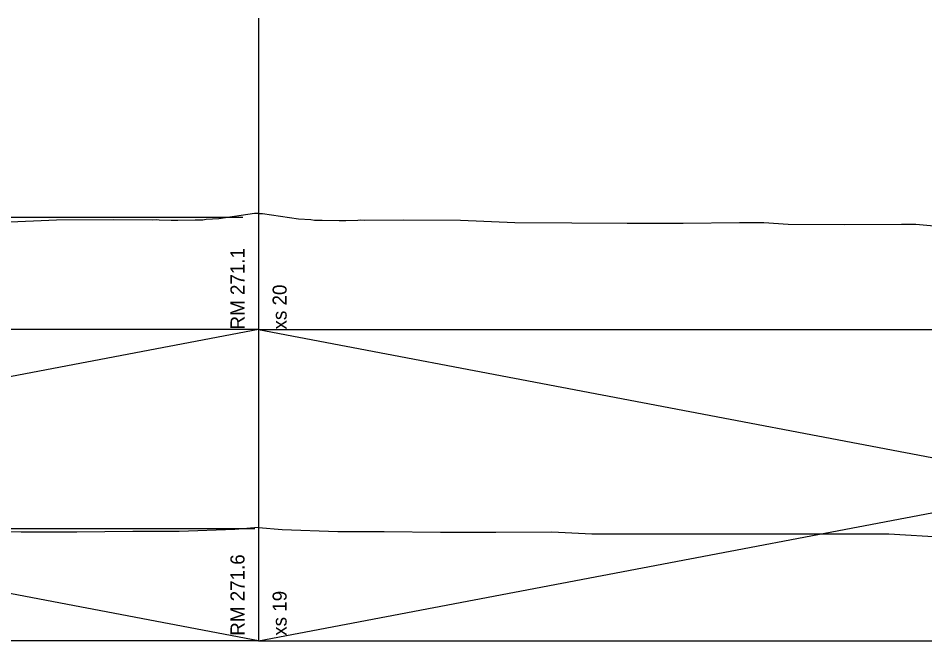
# Model space of a CAD drawing. Extents: x -9489 to 16720, y -4790 to 1662.
# Drawn here: x -2037 to 2806, y -4790 to -1466 of the extents above; entities that cross this region are included whole.
import ezdxf

# ---------------------------------------------------------------- set-up
doc = ezdxf.new("R2010")
doc.units = 0
for name, color, linetype in [('MD_P_Surface_Finished_Grade', 7, 'Continuous'), ('PF_P_Grade_Line', 7, 'Continuous'), ('SC_Scratch1', 7, 'Continuous')]:
    doc.layers.add(name, color=color, linetype=linetype)

msp = doc.modelspace()

# ---------------------------------------------------------------- linework, layer by layer
at = {"layer": 'MD_P_Surface_Finished_Grade'}
for p, q in [((-752.6, -2134.8), (-752.6, -2898.7)), ((-752.6, -3796.7), (-752.6, -4560.6))]:
    msp.add_line(p, q, dxfattribs=at)
at = {"layer": 'PF_P_Grade_Line'}
for p, q in [((-752.6, -3128.2), (-9488.8, -4790.1)), ((-752.6, -4790.1), (-9488.8, -3128.2)), ((-752.6, -3128.2), (7983.7, -4790.1)), ((-752.6, -4790.1), (7983.7, -3128.2))]:
    msp.add_line(p, q, dxfattribs=at)
at = {"layer": 'SC_Scratch1'}
for p, q in [((-9391.8, -2528.2), (-836.4, -2528.2)), ((-9391.8, -4190.1), (-772.7, -4190.1))]:
    msp.add_line(p, q, dxfattribs=at)
for points in [[(-752.6, -1466.4), (-752.6, -3128.2), (-9488.8, -3128.2)], [(-752.6, -1466.4), (-752.6, -3128.2), (7983.7, -3128.2)], [(-752.6, -2509.2), (-773.6, -2508.7), (-965.6, -2538.2), (-1031.6, -2541.2), (-1050.6, -2544.2), (-1091.6, -2545.2), (-1183.6, -2545.7), (-1202.6, -2546.2), (-1218.6, -2547.2), (-1282.6, -2544.2), (-1297.6, -2543.7), (-1317.6, -2543.8), (-1527.6, -2543.7), (-1831.6, -2545.2), (-2120.6, -2557.2)], [(-752.6, -2509.2), (-731.6, -2508.7), (-539.6, -2538.2), (-473.6, -2541.2), (-454.6, -2544.2), (-413.6, -2545.2), (-321.6, -2545.7), (-302.6, -2546.2), (-286.6, -2547.2), (-222.6, -2544.2), (-207.6, -2543.7), (-187.6, -2543.8), (22.4, -2543.7), (326.4, -2545.2), (615.4, -2557.2), (920.4, -2559.7), (1216.4, -2560.2), (1515.4, -2560.2), (1816.4, -2557.2), (1835.4, -2556.7), (1945.4, -2557.7), (2075.4, -2565.7), (2378.4, -2567.2), (2680.4, -2566.2), (2758.4, -2565.2), (2855.4, -2575.7)], [(-752.6, -3128.2), (-752.6, -4790.1), (-9488.8, -4790.1)], [(-752.6, -3128.2), (-752.6, -4790.1), (7983.7, -4790.1)], [(-752.6, -4185.1), (-878.6, -4195.1), (-1176.6, -4205.6), (-1237.6, -4206.1), (-1423.6, -4207.1), (-1723.6, -4209.1), (-2020.6, -4210.6), (-2318.6, -4208.6)], [(-752.6, -4185.1), (-626.6, -4195.1), (-328.6, -4205.6), (-267.6, -4206.1), (-81.6, -4207.1), (218.4, -4209.1), (515.4, -4210.6), (813.4, -4208.6), (1027.4, -4218.1), (2613.4, -4218.1), (2911.4, -4237.1)]]:
    msp.add_lwpolyline(points, dxfattribs=at)

# ---------------------------------------------------------------- texts
for s, p in [('RM 271.1', (-827.6, -3128.2)), ('xs 20', (-602.6, -3128.2)), ('RM 271.6', (-827.6, -4763)), ('xs 19', (-602.6, -4763))]:
    msp.add_text(s, height=75, rotation=90, dxfattribs=at).set_placement(p)

doc.saveas('drawing.dxf')
